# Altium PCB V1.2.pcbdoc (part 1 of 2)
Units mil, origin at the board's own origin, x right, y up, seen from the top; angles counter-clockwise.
Board outline 3255.91 x 1171.26 mil, 2 copper layers (Top Layer, Bottom Layer), stack 2.757 mil thick; 72 components, 47 nets, 250 pads, 80 vias.
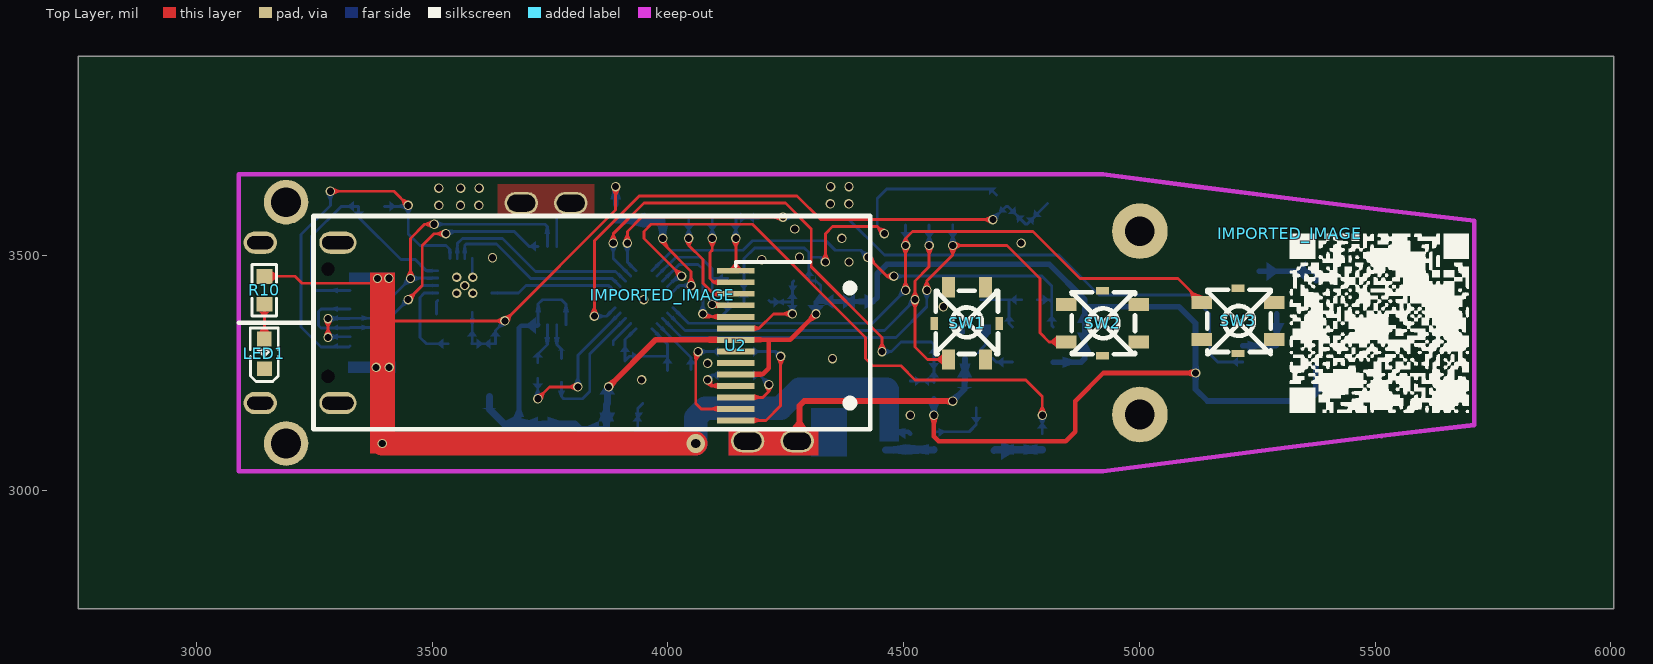
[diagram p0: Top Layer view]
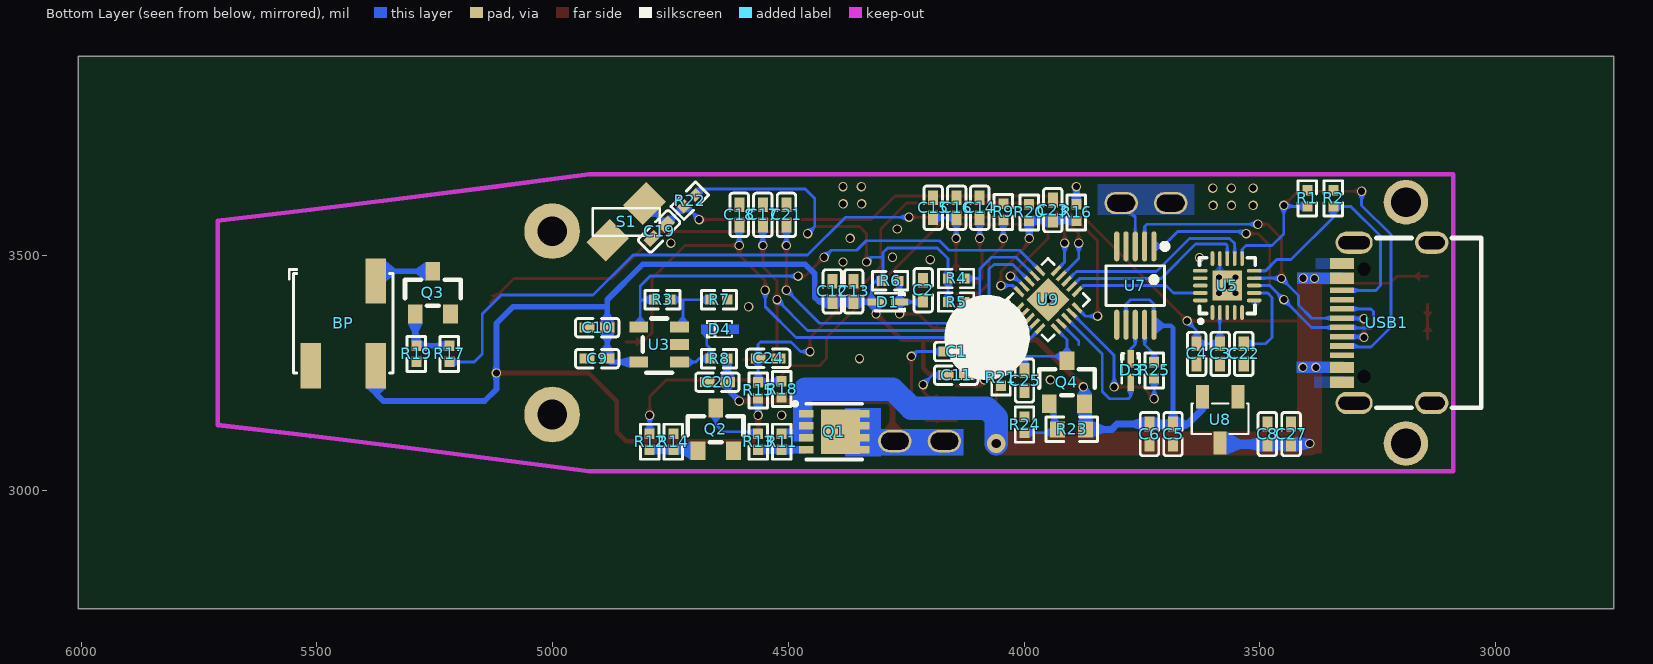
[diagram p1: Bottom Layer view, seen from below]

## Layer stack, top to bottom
Top Layer: signal copper 1.379
Bottom Layer: signal copper 1.378

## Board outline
6005.91,2750 2750,2750 2750,3921.26 6005.91,3921.26

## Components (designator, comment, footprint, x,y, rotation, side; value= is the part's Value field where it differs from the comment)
BP "MLT-5020" BUZ-SMD_3P-L5.2-W5.2-P3.50-BR 5444.32,3355.32 r0 bottom
C1 "CAP_0402" C0402 4144.32,3295.32 r0 bottom
C2 "CAP_0402" C0402 4214.32,3425.32 r270 bottom
C3 "CAP_0402" C0402 3584.32,3290.32 r90 bottom
C4 "CAP_0402" C0402 3634.32,3290.32 r90 bottom
C5 "CAP_0402" C0402 3684.32,3120.24 r90 bottom
C6 "CAP_0402" C0402 3734.32,3120.24 r90 bottom
C8 "CAP_0402" C0402 3484.32,3120.24 r270 bottom
C9 "CAP_0402" C0402 4905.78,3280.32 r180 bottom
C10 "CAP_0402" C0402 4905.78,3345.95 r180 bottom
C11 "CAP_0402" C0402 4144.32,3245.32 r0 bottom
C12 "CAP_0402" C0402 4406.82,3422.82 r270 bottom
C13 "CAP_0402" C0402 4361.82,3422.82 r270 bottom
C14 "CAP_0402" C0402 4094.32,3600.32 r270 bottom
C15 "CAP_0402" C0402 4193.15,3600.32 r270 bottom
C16 "CAP_0402" C0402 4143.15,3600.32 r270 bottom
C17 "CAP_0402" C0402 4554.32,3585.32 r270 bottom
C18 "CAP_0402" C0402 4604.32,3585.32 r90 bottom
C19 "CAP_0402" C0402 4774.32,3550.32 r135 bottom
C20 "CAP_0402" C0402 4650.78,3230.32 r180 bottom
C21 "CAP_0402" C0402 4504.32,3585.32 r270 bottom
C22 "CAP_0402" C0402 3534.32,3290.32 r270 bottom
C23 "CAP_0402" C0402 3939.32,3595.32 r270 bottom
C24 "CAP_0402" C0402 4542.93,3280.83 r0 bottom
C25 "CAP_0402" C0402 3999.32,3233.86 r90 bottom
C27 "CAP_0402" C0402 3433.93,3120.24 r270 bottom
D1 "1N4148" SOD-523_L1.2-W0.8-LS1.6-RD 4289.32,3400.32 r0 bottom
D3 "1N4148WS" SOD-523_L1.2-W0.8-LS1.6-RD 3774.32,3255.32 r270 bottom
D4 "BZX584C3V3" SOD-523F_L1.2-W0.8-LS1.7-RD 4645.45,3342.82 r180 bottom
IMPORTED_IMAGE "IMPORTED_IMAGE" IMPORTED_IMAGE 3988.65,3415.05 r0 top
IMPORTED_IMAGE "IMPORTED_IMAGE" IMPORTED_IMAGE 5319.32,3545.32 r0 top
LED1 "LED_0603-R" LED0603-RD_BLUE 3144.32,3290.32 r90 top
Q1 "SE30P12D" DFN-8_L3.0-W3.0-P0.65-BL 4403.1,3125.32 r270 bottom
Q2 "S8050" SOT-23_L2.9-W1.3-P1.90-LS2.4-BR 4654.32,3130.32 r270 bottom
Q3 "S8050_NPN" SOT-23_L2.9-W1.3-P1.90-LS2.4-BR 5254.32,3420.32 r270 bottom
Q4 "AO3401A_P" SOT-23_L2.9-W1.3-P1.90-LS2.4-BR 3909.32,3230.32 r270 bottom
R1 "Res_0402" R0402 3399.32,3620.32 r270 bottom
R2 "Res_0402" R0402 3344.32,3620.32 r270 bottom
R3 "Res_0402" R0402 4767.28,3405.32 r0 bottom
R4 "Res_0402" R0402 4144.32,3450.32 r0 bottom
R5 "Res_0402" R0402 4144.32,3400.32 r0 bottom
R6 "Res_0402" R0402 4284.32,3445.32 r0 bottom
R7 "Res_0402" R0402 4647.28,3405.32 r0 bottom
R8 "Res_0402" R0402 4647.28,3280.32 r0 bottom
R9 "Res_0402" R0402 4044.32,3591.48 r270 bottom
R10 "Res_0402" R0603 3144.32,3425.32 r90 top
R11 "Res_0402" R0402 4514.32,3104.18 r90 bottom
R12 "Res_0402" R0402 4794.32,3104.18 r90 bottom
R13 "Res_0402" R0402 4564.32,3104.18 r270 bottom
R14 "Res_0402" R0402 4744.32,3104.18 r270 bottom
R15 "Res_0402" R0402 4564.39,3212.87 r270 bottom
R16 "Res_0402" R0402 3889.32,3590.32 r90 bottom
R17 "Res_0402" R0402 5219.32,3290.32 r90 bottom
R18 "B57221V2103J060" R0402 4514.39,3215.83 r90 bottom
R19 "Res_0402" R0402 5289.32,3290.32 r90 bottom
R20 "Res_0402" R0402 3989.32,3590.32 r270 bottom
R21 "Res_0402" R0402 4049.32,3240.32 r90 bottom
R22 "Res_0402" R0402 4709.32,3615.32 r135 bottom
R23 "NC" R0603 3899.32,3130.32 r180 bottom
R24 "10K" R0402 3999.32,3140.32 r270 bottom
R25 "Res_0402" R0402 3724.32,3255.32 r90 bottom
S1 "BL-2030" SMD-Pan1.5*0.8-2P-S2.8 4844.32,3570.32 r135 bottom
SW1 "TS3315A" SW-SMD_4P-L3.4-W3.4-P2.00-LS4.0_TS3315A160GF 4634.32,3355.32 r90 top
SW2 "TS3315A" SW-SMD_4P-L3.4-W3.4-P2.00-LS4.0_TS3315A160GF 4921.68,3355.32 r0 top
SW3 "TS3315A" SW-SMD_4P-L3.4-W3.4-P2.00-LS4.0_TS3315A160GF 5209.32,3360.32 r0 top
U2 "SSD1306-14Pin_0.91_JX" SSD1306-14PIN_0.91_JX 4183.45,3308.08 r270 top
U3 "LM321MFX" SOT-23-5_L2.9-W1.6-P0.95-LS2.8-BL 4774.32,3310.32 r90 bottom
U5 "CH224D" QFN20_3X3 3569.32,3435.32 r180 bottom
U7 "CH340E" MSOP-10_L3.0-W3.0-P0.50-LS5.0-BL 3764.32,3435.32 r0 bottom
U8 "HE2021A30HMR" SOT-23-3_L2.9-W1.6-P1.90-LS2.8-BR-CW 3584.32,3150.32 r90 bottom
U9 "STC8H1K17-36I-QFN20" QFN-20_L3.0-W3.0-P0.40-BL-EP1.7 3949.32,3405.32 r225 bottom
USB1 "KH-TYPE-C-16P" USB-C-SMD_KH-TYPE-C-16P 3230.69,3356.3 r90 bottom

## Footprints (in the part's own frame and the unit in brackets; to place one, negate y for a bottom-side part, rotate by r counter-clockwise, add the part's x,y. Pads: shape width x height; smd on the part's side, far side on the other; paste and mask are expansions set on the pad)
BUZ-SMD_3P-L5.2-W5.2-P3.50-BR [mm]
  rect 1.12x2.425 smd: 1(1.75,2.288) 2(-1.75,2.288) 3(-1.75,-2.288)
  silkscreen extent -2.68,-2.9 2.9,2.68
C0402 [mm]
  rect 0.79x0.54 smd: 1(-0.545,0) 2(0.545,0)
  silkscreen extent -1.17,-0.5 1.17,0.5
DFN-8_L3.0-W3.0-P0.65-BL [mm]
  rect 0.4x0.8 smd: 1(-0.975,-1.5) 2(-0.325,-1.5) 3(0.325,-1.5) 4(0.975,-1.5) 5(0.975,1.5) 6(0.325,1.5) 7(-0.325,1.5) 8(-0.975,1.5)
  rect 2.4x2.1 smd: 9(0,0.35)
  silkscreen extent -1.6,-2.2 1.5,1.5
IMPORTED_IMAGE [mil]
LED0603-RD_BLUE [mil]
  rect 31.5x31.5 smd: 1(-31.5,-0.1) 2(31.5,0.1)
  silkscreen extent -59,-29 55,30
MSOP-10_L3.0-W3.0-P0.50-LS5.0-BL [mil]
  oval 11x63.8 smd: 1(-39.4,-83.1) 2(-19.7,-83.1) 3(0,-83.1) 4(19.7,-83.1) 5(39.4,-83.1) 6(39.4,83.1) 7(19.7,83.1) 8(0,83.1) 9(-19.7,83.1) 10(-39.4,83.1)
  silkscreen extent -69,-89 62,42
QFN20_3X3 [mm]
  rect 1.6x1.6 smd: 0(0,0)
  round 0.508 hole 0.356: 0(0,0)
  oval 0.2x0.8 smd: 1(-0.8,-1.451) 2(-0.4,-1.451) 3(0,-1.451) 4(0.4,-1.451) 5(0.8,-1.451) 11(0.8,1.451) 12(0.4,1.451) 13(0,1.451) 14(-0.4,1.451) 15(-0.8,1.451)
  oval 0.8x0.2 smd: 6(1.451,-0.8) 7(1.451,-0.4) 8(1.451,0) 9(1.451,0.4) 10(1.451,0.8) 16(-1.451,0.8) 17(-1.451,0.4) 18(-1.451,0) 19(-1.451,-0.4) 20(-1.451,-0.8)
  silkscreen extent -1.53,-2.03 1.5,1.5
QFN-20_L3.0-W3.0-P0.40-BL-EP1.7 [mm]
  rect 0.2x0.665 smd: 1(-0.8,-1.407) 2(-0.4,-1.407) 3(0,-1.407) 4(0.4,-1.407) 5(0.8,-1.407) 11(0.8,1.407) 12(0.4,1.407) 13(0,1.407) 14(-0.4,1.407) 15(-0.8,1.407)
  rect 0.665x0.2 smd: 6(1.407,-0.8) 7(1.407,-0.4) 8(1.407,0) 9(1.407,0.4) 10(1.407,0.8) 16(-1.407,0.8) 17(-1.407,0.4) 18(-1.407,0) 19(-1.407,-0.4) 20(-1.407,-0.8)
  rect 1.65x1.65 smd: 21(0,0)
  silkscreen extent -1.58,-2.11 1.58,1.58
R0402 [mm]
  rect 0.566x0.54 smd: 1(-0.433,0) 2(0.433,0)
  silkscreen extent -0.94,-0.5 0.94,0.5
R0603 [mil]
  rect 31.75x34.02 smd: 1(-29.66,0) 2(29.66,0)
  silkscreen extent -55,-26 55,26
SMD-Pan1.5*0.8-2P-S2.8 [mil]
  rect 70x59.1 smd: 1(-55.12,0) 2(55.12,0)
  silkscreen extent -71,-71 71,71
SOD-523_L1.2-W0.8-LS1.6-RD [mm]
  rect 0.93x0.36 smd: 1(-0.635,0) 2(0.635,0)
  silkscreen extent -0.91,-0.55 0.68,0.55
SOD-523F_L1.2-W0.8-LS1.7-RD [mil]
  Top Layer region: -40.01,9.7 -16.01,9.7 -16.01,-9.3 -40.01,-9.3
  Top Layer region: 15.99,9.3 39.99,9.3 39.99,-9.7 15.99,-9.7
  silkscreen extent -29,-19 26,19
SOT-23-3_L2.9-W1.6-P1.90-LS2.8-BR-CW [mil]
  rect 49.2x27.6 smd: 1(49.2,-37.4) 2(-49.2,0) 3(49.2,37.4)
  silkscreen extent -30,-60 35,60
SOT-23-5_L2.9-W1.6-P0.95-LS2.8-BL [mil]
  rect 23.6x39.4 smd: 1(-37.4,-43.3) 2(0,-43.3) 3(37.4,-43.3) 4(37.4,43.3) 5(-37.4,43.3)
  silkscreen extent -60,-27 55,35
SOT-23_L2.9-W1.3-P1.90-LS2.4-BR [mm]
  rect 1x0.8 smd: 1(1.15,-0.95) 2(1.15,0.95) 3(-1.15,0)
  silkscreen extent -0.7,-1.5 0.7,1.5
SSD1306-14PIN_0.91_JX [mm]
  rect 0.32x2 smd: 1(4.03,-1) 2(3.41,-1) 3(2.79,-1) 4(2.17,-1) 5(1.55,-1) 6(0.93,-1) 7(0.31,-1) 8(-0.31,-1) 9(-0.93,-1) 10(-1.55,-1) 11(-2.17,-1) 12(-2.79,-1) 13(-3.41,-1) 14(-4.03,-1)
  silkscreen extent -6.99,-23.75 4.51,6.25
SW-SMD_4P-L3.4-W3.4-P2.00-LS4.0_TS3315A160GF [mil]
  rect 43.3x27.6 smd: 1(-76.8,39.4) 2(76.8,39.4) 3(-76.8,-39.4) 4(76.8,-39.4)
  rect 27.6x15.7 smd: 5(0,69.1) 5(0,-69.1)
  silkscreen extent -65,-66 69,66
USB-C-SMD_KH-TYPE-C-16P [mm]
  oval 1.2x2 hole 0.7 slot 1.7 at 90 deg: 1(-4.32,1.765) 2(4.32,1.765)
  oval 1.2x1.8 hole 0.7 slot 1.4 at 90 deg: 3(-4.32,-2.415) 4(4.32,-2.415)
  rect 0.3x1.3 smd: A1(-3.35,2.415) A4(-2.55,2.415) A5(-1.25,2.415) A6(-0.25,2.415) A7(0.25,2.415) A8(1.25,2.415) A9(2.55,2.415) A12(3.35,2.415) B1(3.05,2.415) B4(2.25,2.415) B5(1.75,2.415) B6(0.75,2.415) B7(-0.75,2.415) B8(-1.75,2.415) B9(-2.25,2.415) B12(-3.05,2.415)
  Multi-Layer board cut-out: -2.89,1.585 -2.738,1.55 -2.616,1.453 -2.549,1.313 -2.549,1.157 -2.616,1.017 -2.738,0.92 -2.89,0.885 -2.89,0.885 -3.042,0.92 -3.164,1.017 -3.231,1.157 -3.231,1.313 -3.164,1.453 -3.042,1.55 -2.89,1.585
  Multi-Layer board cut-out: 2.89,1.585 3.042,1.55 3.164,1.453 3.231,1.313 3.231,1.157 3.164,1.017 3.042,0.92 2.89,0.885 2.89,0.885 2.738,0.92 2.616,1.017 2.549,1.157 2.549,1.313 2.616,1.453 2.738,1.55 2.89,1.585
  silkscreen extent -4.57,-5.08 4.57,0.57

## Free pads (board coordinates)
  round 94.49 hole 62.99: 1(3190.39,3100.39) 1(3190.39,3612.2)
  oval 70.87x47.24 hole 36 slot 59.06 at 0 deg: 1(3794.32,3610.32) 2(3689.32,3610.32) 2(4274.32,3105.32) 3(4169.32,3105.32)
  round 118.11 hole 62.99: 1(5001.3,3550.79) 2(5001.3,3161.81)

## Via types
v1: diameter 20, hole 15, Top Layer to Bottom Layer, 75 vias
v2: diameter 20, hole 12, Top Layer to Bottom Layer, 4 vias
v3: diameter 40, hole 20, Top Layer to Bottom Layer, 1 vias

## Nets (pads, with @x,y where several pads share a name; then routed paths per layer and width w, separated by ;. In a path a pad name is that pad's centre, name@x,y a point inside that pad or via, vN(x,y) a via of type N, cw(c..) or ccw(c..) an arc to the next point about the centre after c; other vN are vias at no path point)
$2N4674: Q3.1 R17.2 R19.2 | length 138.7
  Bottom Layer w12: R17.2@5219.32,3307.36 R19.2@5289.32,3307.36 5291.72,3309.76 Q3.1@5291.72,3375.04
$2N7734: Q2.3 R13.1 | length 133.2
  Bottom Layer w6: R13.1@4564.32,3121.22 4568.42,3125.32 4639.32,3125.32 4654.32,3140.32 Q2.3@4654.31,3175.6
$2N8074: Q2.1 R12.1 R14.2 | length 103.5
  Bottom Layer w15: Q2.1@4691.72,3085.04 4693.81,3087.14 R14.2@4744.32,3087.14 R12.1@4794.32,3087.14
$2N8936: R3.1 R7.2 U3.3 | length 146.5
  Bottom Layer w6: R7.2@4664.32,3405.32 4723.94,3405.32 ; U3.3@4731.02,3347.72 4723.94,3354.8 4723.94,3405.32 ; R3.1@4750.24,3405.32 4723.94,3405.32
$2N9036: R8.2 U3.1 | length 136.2
  Bottom Layer w6: 4673.45,3343.02 4673.45,3309.45 4664.32,3300.32 R8.2@4664.32,3280.32 4689.32,3280.32 4696.72,3272.92 U3.1@4731.02,3272.92
$2N15913: C22.1 U5.7 | length 192.3
  Bottom Layer w6: U5.7@3512.18,3419.57 3483.57,3419.57 3474.32,3410.32 3474.32,3325.32 3487.86,3311.78 C22.1@3534.32,3311.78
$2N17785: LED1.2 R10.1 | length 73.9
  Top Layer w6: LED1.2@3144.22,3321.82 3144.32,3321.92 R10.1@3144.32,3395.66
$2N21898: C1.1 U2.2 | length 260.1
  Top Layer w6: v1(4064.32,3295.32) 4059.32,3290.32 4059.32,3185.32 4070.81,3173.83 U2.2@4144.08,3173.83
  Bottom Layer w6: v1(4064.32,3295.32) C1.1@4122.86,3295.32
$2N21899: C1.2 U2.1 | length 290.7
  Top Layer w6: U2.1@4144.08,3149.42 4208.41,3149.42 4239.32,3180.32 v1(4239.32,3285.32)
  Bottom Layer w6: C1.2@4165.78,3295.32 4229.32,3295.32 v1(4239.32,3285.32)
$2N22010: C11.1 U2.4 | length 110.6
  Top Layer w6: v1(4084.32,3235.32) 4084.32,3230.32 4091.99,3222.65 U2.4@4144.08,3222.65
  Bottom Layer w6: v1(4084.32,3235.32) 4094.32,3245.32 C11.1@4122.86,3245.32
$2N22011: C11.2 U2.3 | length 146.7
  Top Layer w6: U2.3@4144.08,3198.24 4201.53,3198.24 4214.32,3211.02 v1(4214.32,3225.32)
  Bottom Layer w6: C11.2@4165.78,3245.32 4194.32,3245.32 v1(4214.32,3225.32)
$2N24051: C2.2 D1.1 R6.1 U2.9 | length 255.6
  Top Layer w6: U2.9@4144.08,3344.69 4193.68,3344.69 4224.32,3375.32 v1(4264.32,3375.32)
  Bottom Layer w6: C2.2@4214.32,3403.86 4217.86,3400.32 D1.1@4264.32,3400.32 ; v1(4264.32,3375.32) D1.1@4264.32,3400.32 ; R6.1@4267.28,3445.32 4264.32,3442.36 D1.1@4264.32,3400.32
$2N27198: R9.2 U2.12 | length 225.6
  Top Layer w6: v1(4044.32,3535.32) 4044.32,3520.32 4074.32,3490.32 4074.32,3440.32 4096.72,3417.92 U2.12@4144.08,3417.92
  Bottom Layer w6: v1(4044.32,3535.32) R9.2@4044.32,3574.44
$2N27436: C14.2 U2.13 | length 188.7
  Top Layer w6: v1(4094.32,3535.32) 4094.32,3510.32 4089.32,3505.32 4089.32,3450.32 4097.31,3442.33 U2.13@4144.08,3442.33
  Bottom Layer w6: v1(4094.32,3535.32) C14.2@4094.32,3578.86
$2N29185: C15.2 C16.2 U2.14 | length 162.7
  Top Layer w6: U2.14@4144.08,3466.74 4144.32,3466.97 v1(4144.32,3535.32)
  Bottom Layer w6: v1(4144.32,3535.32) 4144.32,3577.7 C16.2@4143.15,3578.86 C15.2@4193.15,3578.86
$2N43776: Q1.4 R11.1 R13.2 | length 102.2
  Bottom Layer w15: Q1.4@4462.16,3086.93 4564.11,3086.93 R13.2@4564.32,3087.14
$2N50518: BP.3 Q3.3 | length 140.5
  Bottom Layer w12: Q3.3@5254.31,3465.6 5374.04,3465.6 5375.42,3464.22 BP.3@5375.42,3445.38
$2N65253: R21.2 U9.4 | length 127.4
  Bottom Layer w6: U9.4@3977.36,3355 4049.32,3283.05 R21.2@4049.32,3257.36
$2N78998: Q4.1 R23.1 R24.2 | length 139.3
  Bottom Layer w6: R23.1@3928.98,3130.32 3936.02,3123.28 R23.1@3936.36,3123.28 ; Q4.1@3946.72,3185.04 3936.36,3174.68 R23.1@3936.36,3123.28 ; R24.2@3999.32,3123.28 R23.1@3936.36,3123.28
$2N81785: D3.1 U7.8 | length 76
  Bottom Layer w6: U7.8@3764.32,3352.22 3764.32,3310.32 3774.32,3300.32 D3.1@3774.32,3280.32
$2N81968: R25.2 U7.9 | length 88.3
  Bottom Layer w6: R25.2@3724.32,3272.36 3724.32,3290.32 3744.62,3310.62 U7.9@3744.62,3352.22
+3.3V: BP.2 C5.2 C6.2 C9.2 C10.2 C12.2 C13.2 D1.2 Q4.2 R4.2 R5.2 R6.2 R15.2 R22.2 R23.2 U2.5 U2.8 U3.5 U7.7 U7.10 U8.3 | length 4719.7
  Top Layer w6: v1(4334.32,3485.32) 4334.32,3545.32 4349.32,3560.32 4444.32,3560.32 v1(4459.32,3545.32)
  Top Layer w10: U2.5@4144.08,3247.06 4201.05,3247.06 4214.32,3260.32 4214.32,3320.32 ; U2.8@4144.08,3320.28 4214.32,3320.32 ; v1(4314.32,3375.32) 4259.32,3320.32 4214.32,3320.32 ; v1(4564.32,3160.32) 4564.32,3115.32 4574.32,3105.32 4844.32,3105.32 4864.32,3125.32 4864.32,3190.32 4923.88,3249.88 v1(5119.32,3249.88)
  Top Layer w12: v1(3874.32,3220.32) 3974.27,3320.28 U2.8@4144.08,3320.28
  Bottom Layer w6: U7.10@3724.92,3352.22 3724.92,3395.92 3734.32,3405.32 3774.32,3405.32 3784.02,3395.62 U7.7@3784.02,3352.22 ; R5.2@4161.36,3400.32 R4.2@4161.36,3450.32 4161.36,3492.36 4184.32,3515.32 4289.32,3515.32 4299.32,3505.32 4299.32,3495.32 ; D1.2@4324.32,3400.32 4324.32,3401.36 4324.32,3435.32 4314.32,3445.32 R6.2@4301.36,3445.32 4299.32,3447.36 4299.32,3495.32 ; v1(4334.32,3485.32) 4324.32,3495.32 4299.32,3495.32 ; v1(4459.32,3545.32) 4444.32,3560.32 4444.32,3620.32 4464.32,3640.32 4684.32,3640.32 R22.2@4697.27,3627.37
  Bottom Layer w10: C5.2@3684.32,3141.7 3684.32,3345.32 3689.32,3350.32 3723.02,3350.32 U7.10@3724.92,3352.22 ; v1(4314.32,3375.32) D1.2@4314.32,3400.32 4315.36,3401.36 4324.32,3401.36 C13.2@4361.82,3401.36 C12.2@4406.82,3401.36 ; v1(4564.32,3160.32) 4564.32,3195.75 R15.2@4564.39,3195.83
  Bottom Layer w12: C12.2@4406.82,3401.36 4435.36,3401.36 4444.32,3410.32 4444.32,3460.32 4464.32,3480.32 4809.32,3480.32 4884.32,3405.32 4884.32,3390.32 ; U3.5@4817.62,3272.92 4876.92,3272.92 C9.2@4884.32,3280.32 C10.2@4884.32,3345.95 4884.32,3390.32 ; BP.2@5375.42,3265.26 5374.32,3264.16 5374.32,3205.32 5359.32,3190.32 5144.32,3190.32 5119.32,3215.32 v1(5119.32,3249.88) 5119.32,3355.32 5084.32,3390.32 4884.32,3390.32
  Bottom Layer w15: U8.3@3621.72,3199.52 3621.72,3172.92 3654.32,3140.32 3732.94,3140.32 C6.2@3734.32,3141.7 3802.94,3141.7 3814.32,3130.32 R23.2@3869.66,3130.32 3869.66,3182.79 Q4.2@3871.91,3185.04 3871.91,3217.92 v1(3874.32,3220.32)
ADD: C18.1 SW2.3 U9.3 | length 1188.6
  Top Layer w6: v1(4549.32,3425.32) 4549.32,3445.32 4604.32,3500.32 v1(4604.32,3520.32) 4719.32,3520.32 4789.32,3450.32 4789.32,3335.32 4808.72,3315.92 SW2.3@4844.88,3315.92
  Bottom Layer w6: U9.3@3988.5,3366.14 4029.32,3325.32 4484.32,3325.32 4549.32,3390.32 v1(4549.32,3425.32) ; v1@4604.32,3525.32 C18.1@4604.32,3563.86
BEEP: R17.1 U9.15 | length 1585.4
  Top Layer w6: v1(3914.32,3525.32) 3914.32,3550.32 3944.32,3580.32 v1(4244.32,3580.32)
  Bottom Layer w6: v1(3914.32,3525.32) 3914.32,3484.87 U9.15@3932.41,3466.78 ; v1(4244.32,3580.32) 4379.32,3580.32 4459.32,3500.32 4829.32,3500.32 4914.32,3415.32 5109.32,3415.32 5149.32,3375.32 5149.32,3290.32 5166.36,3273.28 R17.1@5219.32,3273.28
CC1: R1.2 U5.11 USB1.A5 | length 844.4
  Top Layer w6: v1(3284.32,3635.32) 3419.32,3635.32 v1(3449.32,3605.32)
  Bottom Layer w6: v1(3284.32,3635.32) 3284.32,3605.32 3222.32,3543.32 3222.32,3347.32 3264.32,3305.32 3324.01,3305.32 USB1.A5@3325.77,3307.09 ; R1.2@3399.32,3603.28 v1@3449.32,3603.28 ; v1(3449.32,3605.32) v1@3449.32,3603.28 ; U5.11@3537.81,3492.45 3537.81,3511.82 3529.32,3520.32 3474.32,3520.32 3449.32,3545.32 v1@3449.32,3603.28
CC2: R2.2 U5.10 USB1.B5 | length 554.6
  Bottom Layer w6: USB1.B5@3325.77,3425.2 3254.44,3425.2 3244.32,3435.32 3244.32,3540.32 3307.28,3603.28 R2.2@3344.32,3603.28 3344.32,3580.32 3434.32,3490.32 3464.32,3490.32 3487.82,3466.82 U5.10@3512.18,3466.82
CFG1: U5.19 U9.11 | length 273.4
  Bottom Layer w6: U5.19@3626.45,3419.57 3683.57,3419.57 3699.32,3435.32 3874.77,3435.32 U9.11@3887.86,3422.23
CFG2: U5.13 U9.12 | length 396.1
  Bottom Layer w6: U5.13@3569.31,3492.45 3569.31,3520.31 3572.32,3523.32 3636.32,3523.32 3709.32,3450.32 3882.04,3450.32 U9.12@3899,3433.36
CFG3: U5.12 U9.13 | length 431.8
  Bottom Layer w6: U5.12@3553.56,3492.45 3553.56,3519.56 ; 3554.32,3520.32 3553.56,3519.56 ; U9.13@3910.14,3444.5 3889.32,3465.32 3719.32,3465.32 3649.32,3535.32 3564.32,3535.32 3553.56,3524.56 3553.56,3519.56
DM: U5.9 U7.2 USB1.A7 USB1.B7 | length 798.7
  Top Layer w6: v1(3279.32,3325.32) v1(3279.32,3365.32) ; v1(3454.32,3450.32) 3454.32,3535.32 3484.32,3565.32 v1(3504.32,3565.32)
  Bottom Layer w6: v1(3279.32,3325.32) 3280.77,3326.77 USB1.B7@3325.77,3326.77 ; v1(3279.32,3365.32) 3324.96,3365.32 USB1.A7@3325.77,3366.14 3390.14,3366.14 3417.92,3393.93 3417.92,3413.93 3455.06,3451.07 U5.9@3512.18,3451.07 ; v1(3504.32,3565.32) 3739.32,3565.32 3744.62,3560.02 U7.2@3744.62,3518.42
DP: U5.8 U7.1 USB1.A6 USB1.B6 | length 789.6
  Top Layer w6: v1(3449.32,3405.32) 3479.32,3435.32 3479.32,3520.32 3504.32,3545.32 v1(3529.32,3545.32)
  Bottom Layer w6: USB1.B6@3325.77,3385.83 3264.83,3385.83 3259.32,3380.32 3259.32,3350.32 3264.32,3345.32 3324.64,3345.32 USB1.A6@3325.77,3346.46 3390.46,3346.46 v1(3449.32,3405.32) 3479.32,3435.32 U5.8@3512.18,3435.32 ; v1(3529.32,3545.32) 3534.32,3550.32 3674.32,3550.32 3706.22,3518.42 U7.1@3724.92,3518.42
GND: C2.1 C3.1 C4.1 C5.1 C6.1 C8.1 C9.1 C10.1 C12.1 C13.1 C14.1 C15.1 C16.1 C17.1 C18.2 C19.1 C20.1 C21.1 C22.2 C23.1 C24.1 C25.1 C27.1 LED1.1 pad.1 pad.2@3689.32,3610.32 pad.2@5001.3,3161.81 Q2.2 Q3.2 R1.1 R2.1 R7.1 R9.1 R14.1 R18.1 R19.1 R20.1 R21.1 R24.1 S1.1 SW1.3 SW1.5 SW2.1 SW2.5 SW3.3 SW3.5 U2.7 U3.2 U5.0 U5.6 U5.14 U5.15 U7.3 U8.1 U9.7 U9.21 USB1.1 USB1.2 USB1.3 USB1.4 USB1.A1 USB1.A12 USB1.B1 USB1.B12 | length 234.2
  Bottom Layer w6: 3509.32,3375.32 3509.32,3400.96 U5.6@3512.18,3403.82 ; U5.14@3585.06,3492.45 3585.06,3454.64 U5.0@3586.71,3452.99 ; U7.3@3764.32,3518.42 3764.32,3580.32 pad.1@3794.32,3610.32 ; 3884.32,3310.32 3884.32,3318.05 U9.7@3921.27,3355
  other v1: 4514.32,3160.32 3944.32,3235.32 4084.32,3270.32 4349.32,3280.32 4584.32,3390.32 3949.32,3405.32 4384.32,3485.32 4199.32,3490.32 3628.25,3494.38 4279.32,3495.32 4749.32,3525.32 4369.32,3535.32 4269.32,3555.32 3514.6,3605.32 3560.31,3605.32 3599.32,3605.32 4344.95,3608.72 4383.96,3608.72 3514.6,3641.92 3560.73,3641.92 3599.67,3641.92 4345.38,3645.32 4384.32,3645.32
LESSEN: C21.2 SW3.1 U9.1 | length 1381.6
  Top Layer w6: v1(4504.32,3425.32) v1(4504.32,3520.32) 4504.32,3535.32 4519.32,3550.32 4774.32,3550.32 4874.32,3450.32 5081.92,3450.32 SW3.1@5132.52,3399.72
  Bottom Layer w6: U9.1@4010.77,3388.41 4043.86,3355.32 4434.32,3355.32 v1(4504.32,3425.32) ; v1@4504.32,3525.32 C21.2@4504.32,3563.86
MCU-RXD: D3.2 U9.8 | length 285.5
  Bottom Layer w6: D3.2@3774.32,3230.32 3774.32,3200.32 3779.32,3195.32 3819.32,3195.32 3834.32,3210.32 3834.32,3290.32 U9.8@3910.14,3366.14
MCU-TXD: R25.1 U9.9 | length 332.4
  Top Layer w6: v1(3724.32,3195.32) 3749.32,3220.32 v1(3809.32,3220.32)
  Bottom Layer w6: v1(3724.32,3195.32) R25.1@3724.32,3238.28 ; v1(3809.32,3220.32) 3809.32,3287.59 U9.9@3899,3377.28
MCU-VCC: C25.2 Q4.3 U9.5 U9.6 | length 274.1
  Bottom Layer w6: U9.6@3932.41,3343.87 3909.31,3320.77 Q4.3@3909.31,3275.6 3919.04,3285.32 3999.32,3285.32 ; U9.5@3966.22,3343.87 3999.32,3310.77 3999.32,3285.32 ; C25.2@3999.32,3255.32 3999.32,3285.32
NTC-ADC14: C24.2 R15.1 R18.2 U9.14 | length 1148.9
  Top Layer w6: v1(3884.32,3525.32) 3884.32,3545.32 3949.32,3610.32 4249.32,3610.32 4304.32,3555.32 4304.32,3475.32 4454.32,3325.32 v1(4454.32,3295.32)
  Bottom Layer w6: v1(3884.32,3525.32) 3884.32,3492.59 U9.14@3921.27,3455.64 ; v1(4454.32,3295.32) 4474.32,3295.32 4494.32,3315.32 4559.32,3315.32 4564.39,3310.24 C24.2@4564.39,3280.83 R15.1@4564.39,3229.91 4561.43,3232.87 R18.2@4514.39,3232.87
OLED-SCL: R5.1 U2.10 U9.18 | length 349.6
  Top Layer w6: v1(4074.32,3375.32) 4080.54,3369.1 U2.10@4144.08,3369.1
  Bottom Layer w6: U9.18@3988.5,3444.5 4024.32,3480.32 4064.32,3480.32 4074.32,3470.32 v1(4074.32,3375.32) 4079.32,3370.32 4114.32,3370.32 4127.28,3383.28 R5.1@4127.28,3400.32
OLED-SDA: R4.1 U2.11 U9.17 | length 302.4
  Top Layer w6: v1(4094.32,3395.32) 4142.27,3395.32 U2.11@4144.08,3393.51
  Bottom Layer w6: U9.17@3977.36,3455.64 4017.04,3495.32 4069.32,3495.32 4094.32,3470.32 4094.32,3449.85 ; v1(4094.32,3395.32) 4094.32,3449.85 ; R4.1@4127.28,3450.32 4094.78,3450.32 4094.32,3449.85
PW/MODEL: C17.2 SW1.1 U9.2 | length 914.6
  Top Layer w6: v1(4554.32,3520.32) 4554.32,3475.32 4524.32,3445.32 v1(4524.32,3405.32) 4524.32,3305.32 4551.12,3278.52 SW1.1@4594.92,3278.52
  Bottom Layer w6: U9.2@3999.63,3377.28 4036.59,3340.32 4459.32,3340.32 v1(4524.32,3405.32) ; v1@4554.32,3525.32 C17.2@4554.32,3563.86
SLEEP_FLAG: C19.2 R22.1 S1.2 U9.10 | length 1277.5
  Top Layer w6: v1(3844.32,3370.32) 3844.32,3530.32 3939.32,3625.32 4274.32,3625.32 4324.32,3575.32 v1(4689.32,3575.32)
  Bottom Layer w6: v1(3844.32,3370.32) 3869.77,3370.32 U9.10@3887.86,3388.41 ; v1(4689.32,3575.32) 4717.27,3603.27 R22.1@4721.37,3603.27 C19.2@4759.14,3565.5 4761.54,3565.5 S1.2@4805.34,3609.3
T12-ADC0: R3.2 U3.4 U9.16 | length 1034.2
  Top Layer w6: v1(4424.32,3495.32) 4464.32,3455.32 v1(4479.32,3455.32)
  Bottom Layer w6: U9.16@3966.22,3466.78 4009.77,3510.32 4159.48,3510.32 4179.48,3530.32 4335.04,3530.32 4355.04,3510.32 4409.32,3510.32 v1(4424.32,3495.32) ; v1(4479.32,3455.32) 4793.23,3455.32 4814.32,3434.23 4814.32,3400.32 ; R3.2@4784.32,3405.32 4809.32,3405.32 4814.32,3400.32 ; U3.4@4817.62,3347.72 4814.32,3351.02 4814.32,3400.32
T12-ADC1: C23.2 R16.1 R20.2 U9.20 | length 306.8
  Top Layer w6: v1(3989.32,3535.32) 3989.32,3525.32 4049.32,3465.32 v1(4049.32,3435.32)
  Bottom Layer w6: U9.20@4010.77,3422.23 4023.86,3435.32 v1(4049.32,3435.32)
  Bottom Layer w12: R16.1@3889.32,3573.28 R20.2@3989.32,3573.28 v1(3989.32,3535.32)
T12-OUTPUT: C20.2 pad.2@4274.32,3105.32 pad.3 Q1.5 Q1.6 Q1.7 Q1.8 Q1.9 R8.1 | length 506.9
  Top Layer w12: pad.2@4274.32,3105.32 4279.32,3110.32 4279.32,3180.32 4289.32,3190.32 v1(4604.32,3190.32)
  Bottom Layer w12: v1(4604.32,3190.32) 4629.32,3215.32 C20.2@4629.32,3230.32 4630.24,3231.24 R8.1@4630.24,3280.32
T12-PWM: R12.2 U9.19 | length 1274.8
  Top Layer w6: v1(4029.32,3455.32) 3949.32,3535.32 3949.32,3550.32 3964.32,3565.32 4179.32,3565.32 4419.32,3325.32 4419.32,3280.32 4434.32,3265.32 4494.32,3265.32 4524.32,3235.32 4759.32,3235.32 4794.32,3200.32 v1(4794.32,3160.32)
  Bottom Layer w6: U9.19@3999.63,3433.36 4021.59,3455.32 v1(4029.32,3455.32) ; R12.2@4794.32,3121.22 v1(4794.32,3160.32)
VBUS: C3.2 C4.2 C8.2 C27.2 Q1.1 Q1.2 Q1.3 R10.2 R11.2 R16.2 U5.2 U8.2 USB1.A4 USB1.A9 USB1.B4 USB1.B9 | length 2485.1
  Top Layer w6: R10.2@3144.32,3454.98 3209.66,3454.98 3224.32,3440.32 3389.32,3440.32 ; 3404.32,3365.32 3409.32,3360.32 v1(3654.32,3360.32) 3889.32,3595.32 v1(3889.32,3645.32)
  Top Layer w50: v1(3394.32,3100.32) v3(4059.32,3100.32)
  Bottom Layer w6: U5.2@3585.06,3378.19 3585.06,3312.53 C3.2@3584.32,3311.78 C4.2@3634.32,3311.78 3634.32,3340.32 v1(3654.32,3360.32)
  Bottom Layer w10: 4469.32,3125.32 4510.21,3125.32 R11.2@4514.32,3121.22
  Bottom Layer w12: R16.2@3889.32,3607.36 v1(3889.32,3645.32)
  Bottom Layer w20: v1(3394.32,3100.32) 3432.39,3100.32 C27.2@3433.93,3098.78 C8.2@3484.32,3098.78 3581.98,3098.78 U8.2@3584.32,3101.12
  Bottom Layer w50: v3(4059.32,3100.32) 4059.32,3155.32 4079.32,3175.32 4239.32,3175.32 4279.32,3215.32 4464.32,3215.32
  other v1: 3381.51,3261.82 3408.79,3261.82 3384.32,3450.32 3408.48,3450.82
"": BP.1 SW1.2 SW1.4 SW2.2 SW2.4 SW3.2 SW3.4 U2.6 U5.1 U5.3 U5.4 U5.5 U5.16 U5.17 U5.18 U5.20 U7.4 U7.5 U7.6 USB1.A8 USB1.B8
  other v2: 3551.91,3418.69 3586.71,3418.69 3551.91,3452.99 3586.71,3452.99

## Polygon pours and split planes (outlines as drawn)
GND on Bottom Layer (solid, remove dead copper, pour order 0): 3090.02,3040.28 5714.32,3040.28 5714.32,3671.18 3090.02,3671.18
GND on Top Layer (solid, remove dead copper, pour order 1): 3090.02,3040.24 5714.32,3040.24 5714.32,3671.24 3090.02,3671.24

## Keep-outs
Keep-Out Layer:
  lines w10 net "": 4923.27,3041.34 3090,3041.34 3090,3356.3 3090,3671.26 4923.27,3671.26 ; 4923.28,3041.34 cw(c10956.17,-42023.09) 5710.68,3139.77 ; 4923.28,3671.26 ccw(c10956.17,48735.69) 5710.68,3572.83 ; 5710.67,3139.76 5710.67,3572.83

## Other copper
Top Layer:
  region net T12-OUTPUT: 4129.32,3075.32 4319.32,3075.32 4319.32,3130.32 4129.32,3130.32
  region net VBUS: 3369.32,3250.32 3421.32,3250.32 3421.32,3462.32 3369.32,3462.32
  region net VBUS: 3369.32,3079.63 3421.32,3079.63 3421.32,3260.33 3369.32,3260.33
  region net T12-OUTPUT: 4285.32,3146.94 4273.32,3146.94 4258.32,3128.57 4300.32,3124.21
  region net $2N17785: 3141.32,3346.57 3133.82,3337.57 3154.82,3337.57 3147.32,3346.57
  region net PW/MODEL: 4572.12,3275.52 4581.12,3268.02 4581.12,3289.02 4572.12,3281.52
  region net ADD: 4814.23,3312.92 4823.23,3305.42 4823.23,3326.42 4814.23,3318.92
  region net LESSEN: 5108.11,3419.88 5110.87,3406.52 5133.57,3413.52 5116.6,3419.88
  region net $2N29185: 4147.32,3482.04 4141.32,3482.04 4133.82,3473.04 4154.82,3473.04
  region net $2N27436: 4097.31,3439.33 4104.71,3436.03 4104.71,3448.63 4097.31,3445.33
  region net $2N27198: 4096.72,3414.92 4104.71,3411.62 4104.71,3424.22 4096.72,3420.92
  region net OLED-SDA: 4095.71,3398.32 4095.71,3392.32 4104.71,3387.21 4104.71,3399.81
  region net OLED-SCL: 4095.71,3372.1 4095.71,3366.1 4104.71,3362.8 4104.71,3375.4
  region net $2N24051: 4192.45,3341.69 4192.45,3347.69 4183.45,3350.99 4183.45,3338.39
  region net +3.3V: 4086.71,3326.28 4086.71,3314.28 4104.71,3313.98 4104.71,3326.58
  region net +3.3V: 4198.45,3315.32 4198.45,3325.32 4183.45,3326.58 4183.45,3313.98
  region net +3.3V: 4198.45,3252.06 4183.45,3253.36 4183.45,3240.76 4198.45,3242.06
  region net $2N22010: 4095.71,3219.65 4104.71,3216.35 4104.71,3228.95 4095.71,3225.65
  region net $2N22011: 4192.45,3201.24 4183.45,3204.54 4183.45,3191.94 4192.45,3195.24
  region net $2N21898: 4095.71,3170.83 4104.71,3167.53 4104.71,3180.13 4095.71,3176.83
  region net $2N21899: 4192.45,3152.42 4183.45,3155.72 4183.45,3143.12 4192.45,3146.42
  region net VBUS: 3170.32,3457.98 3161.32,3465.48 3161.32,3444.48 3170.32,3451.98
  region net $2N17785: 3141.32,3370.79 3147.32,3370.79 3154.82,3379.79 3133.82,3379.79
  region net $2N29185: 4136.82,3528.71 4141.32,3518.32 4147.32,3518.32 4151.82,3528.71
  region net $2N27436: 4086.82,3528.71 4091.32,3518.32 4097.32,3518.32 4101.82,3528.71
  region net $2N27198: 4036.82,3528.71 4041.32,3520.32 4047.32,3520.32 4051.82,3528.71
  region net $2N24051: 4257.7,3382.82 4247.32,3378.32 4247.32,3372.32 4257.7,3367.82
  region net +3.3V: 4304.34,3375.95 4298.76,3366.84 4305.83,3359.76 4314.94,3365.34
  region net CC1: 3290.93,3627.82 3301.32,3632.32 3301.32,3638.32 3290.93,3642.82
  region net CC1: 3449.94,3615.3 3439.42,3619.46 3435.17,3615.22 3439.34,3604.69
  region net DM: 3271.82,3358.71 3276.32,3348.32 3282.32,3348.32 3286.82,3358.71
  region net DM: 3286.82,3331.94 3282.32,3342.32 3276.32,3342.32 3271.82,3331.94
  region net VBUS: 3376.82,3443.71 3389.32,3437.32 3389.32,3443.32 3391.82,3443.71
  region net DP: 3522.7,3552.82 3512.32,3548.32 3512.32,3542.32 3522.7,3537.82
  region net DP: 3459.3,3404.69 3463.46,3415.22 3459.22,3419.46 3448.69,3415.3
  region net DM: 3497.7,3572.82 3487.32,3568.32 3487.32,3562.32 3497.7,3557.82
  region net DM: 3461.82,3456.94 3457.32,3467.32 3451.32,3467.32 3446.82,3456.94
  region net VBUS: 3647.7,3367.82 3637.32,3363.32 3637.32,3357.32 3647.7,3352.82
  region net VBUS: 3664.3,3359.69 3668.46,3370.22 3664.22,3374.46 3653.69,3370.3
  region net MCU-TXD: 3802.7,3227.82 3792.32,3223.32 3792.32,3217.32 3802.7,3212.82
  region net MCU-TXD: 3734.3,3194.69 3738.46,3205.22 3734.22,3209.46 3723.69,3205.3
  region net OLED-SDA: 4100.93,3387.82 4111.32,3392.32 4111.32,3398.32 4100.93,3402.82
  region net OLED-SCL: 4074.83,3365.33 4088.7,3366.1 4093.47,3372.1 4084.16,3377.08
  region net VBUS: 3881.82,3638.71 3886.32,3628.32 3892.32,3628.32 3896.82,3638.71
  region net T12-ADC1: 3981.82,3528.71 3986.32,3525.32 3992.32,3525.32 3996.82,3528.71
  region net T12-ADC1: 3981.82,3528.71 3992.07,3518.32 4000.56,3518.32 3996.82,3528.71
  region net T12-ADC1: 3981.82,3528.71 3992.07,3518.32 4000.56,3518.32 3996.82,3528.71
  region net +3.3V: 3884.3,3219.69 3890.58,3228.1 3882.1,3236.58 3873.69,3230.3
  region net BEEP: 3921.82,3531.94 3917.32,3542.32 3911.32,3542.32 3906.82,3531.94
  region net NTC-ADC14: 3891.82,3531.94 3887.32,3542.32 3881.32,3542.32 3876.82,3531.94
  region net T12-ADC1: 4056.82,3441.94 4052.32,3452.32 4046.32,3452.32 4041.82,3441.94
  region net T12-PWM: 4029.94,3465.3 4019.42,3469.46 4015.17,3465.22 4019.34,3454.69
  region net SLEEP_FLAG: 3851.82,3376.94 3847.32,3387.32 3841.32,3387.32 3836.82,3376.94
  region net T12-OUTPUT: 4597.7,3197.82 4587.32,3196.32 4587.32,3184.32 4597.7,3182.82
  region net BEEP: 4237.7,3587.82 4227.32,3583.32 4227.32,3577.32 4237.7,3572.82
  region net T12-PWM: 4801.82,3166.94 4797.32,3177.32 4791.32,3177.32 4786.82,3166.94
  region net +3.3V: 5112.7,3257.38 5102.32,3254.88 5102.32,3244.88 5112.7,3242.38
  region net +3.3V: 4556.82,3153.71 4559.32,3143.32 4569.32,3143.32 4571.82,3153.71
  region net LESSEN: 4511.82,3431.94 4507.32,3442.32 4501.32,3442.32 4496.82,3431.94
  region net ADD: 4556.82,3431.94 4552.32,3442.32 4546.32,3442.32 4541.82,3431.94
  region net PW/MODEL: 4531.82,3411.94 4527.32,3422.32 4521.32,3422.32 4516.82,3411.94
  region net PW/MODEL: 4516.82,3398.71 4521.32,3388.32 4527.32,3388.32 4531.82,3398.71
  region net LESSEN: 4496.82,3513.71 4501.32,3503.32 4507.32,3503.32 4511.82,3513.71
  region net LESSEN: 4511.82,3526.94 4507.32,3535.32 4501.32,3535.32 4496.82,3526.94
  region net PW/MODEL: 4546.82,3513.71 4551.32,3503.32 4557.32,3503.32 4561.82,3513.71
  region net ADD: 4596.82,3513.71 4601.32,3503.32 4607.32,3503.32 4611.82,3513.71
  region net ADD: 4610.93,3512.82 4621.32,3517.32 4621.32,3523.32 4610.93,3527.82
  region net T12-ADC0: 4423.69,3485.34 4434.22,3481.18 4438.46,3485.42 4434.3,3495.95
  region net T12-ADC0: 4472.7,3462.82 4464.32,3458.32 4464.32,3452.32 4472.7,3447.82
  region net NTC-ADC14: 4461.82,3301.94 4457.32,3312.32 4451.32,3312.32 4446.82,3301.94
  region net SLEEP_FLAG: 4682.7,3582.82 4672.32,3578.32 4672.32,3572.32 4682.7,3567.82
  region net +3.3V: 4459.94,3555.3 4449.42,3559.46 4445.17,3555.22 4449.34,3544.69
  region net +3.3V: 4341.82,3491.94 4337.32,3502.32 4331.32,3502.32 4326.82,3491.94
  region net $2N22010: 4080.2,3226.21 4089.87,3220.53 4094.11,3224.77 4093.87,3232.38
  region net $2N22011: 4206.82,3218.71 4211.32,3211.02 4217.32,3211.02 4221.82,3218.71
  region net $2N21898: 4054.51,3293.34 4056.32,3280.31 4062.32,3276.85 4067.5,3285.84
  region net $2N21899: 4231.82,3278.71 4236.32,3268.32 4242.32,3268.32 4246.82,3278.71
